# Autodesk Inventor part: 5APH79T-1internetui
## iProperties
Created: 2010-11
Part Number: 5APH79T-1internetui
Document SubType Name: Modeling
Designer: Darius
Author: Darius
Translation Standard: STEP AP203
File Name: 5APH79T-1.STEP
Preprocessor: SolidWorks 2003240
Postprocessor: Build: 272, Release: 10 SP3a - Date: Thu 12/15/2005
Sent Units: MILLIMETERS
Uncertainty: 1e-05
